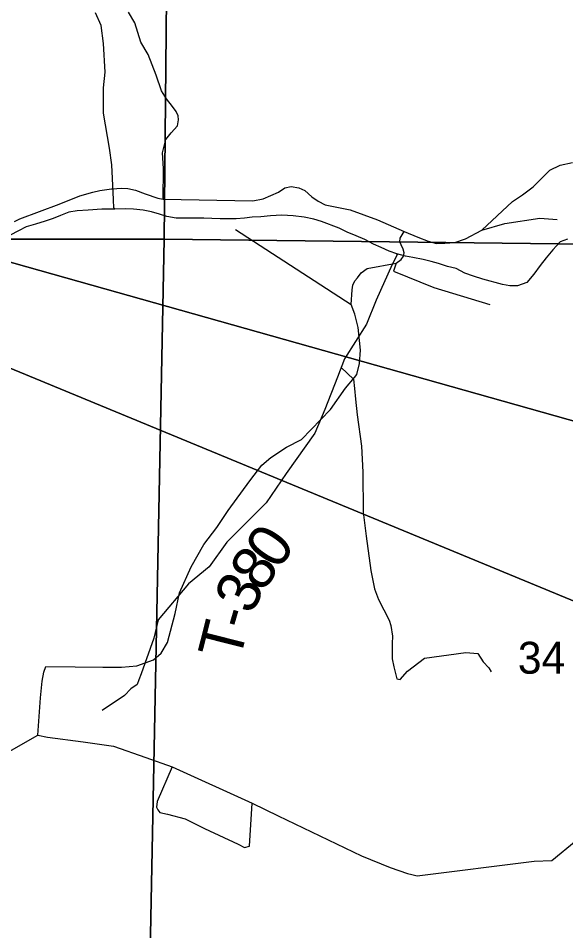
# Model space of a CAD drawing. Extents: x 0 to 34, y 0 to 22.
# Drawn here: x 6.245 to 6.964, y 16.204 to 17.402 of the extents above; entities that cross this region are included whole.
import ezdxf

# ---------------------------------------------------------------- set-up
doc = ezdxf.new("R2010")
doc.units = 0
for name, color, linetype in [('GM_X_County_Road', 7, 'Continuous'), ('GM_X_Minor_River', 7, 'Continuous'), ('GM_X_Section', 7, 'Continuous'), ('GM_X_Section_Text', 7, 'Continuous'), ('GM_X_Township_Road', 7, 'Continuous'), ('GM_X_Township_Road_Text', 7, 'Continuous'), ('SC_Shading1', 7, 'Continuous'), ('SH_Data', 7, 'Continuous')]:
    doc.layers.add(name, color=color, linetype=linetype)

msp = doc.modelspace()

# ---------------------------------------------------------------- linework, layer by layer
at = {"layer": 'GM_X_County_Road'}
for p, q in [((6.9435, 17.2023), (6.9567, 17.2088)), ((6.9567, 17.2088), (6.9733, 17.2121)), ((6.9212, 17.1802), (6.9435, 17.2023)), ((6.5953, 17.1792), (6.6035, 17.1807)), ((6.6035, 17.1807), (6.6138, 17.1792)), ((6.3261, 17.1683), (6.3431, 17.1733)), ((6.3431, 17.1733), (6.3524, 17.1753)), ((6.3524, 17.1753), (6.3677, 17.1775)), ((6.3677, 17.1775), (6.3687, 17.1776)), ((6.3687, 17.1776), (6.3803, 17.1787)), ((6.3803, 17.1787), (6.389, 17.1782)), ((6.389, 17.1782), (6.399, 17.176)), ((6.399, 17.176), (6.4116, 17.171)), ((6.4116, 17.171), (6.4285, 17.1654)), ((6.5666, 17.1645), (6.5868, 17.1735)), ((6.5868, 17.1735), (6.5953, 17.1792)), ((6.6138, 17.1792), (6.6215, 17.1757)), ((6.6215, 17.1757), (6.6305, 17.167)), ((6.8942, 17.1612), (6.9072, 17.17)), ((6.9072, 17.17), (6.9212, 17.1802)), ((6.2472, 17.1381), (6.2988, 17.1577)), ((6.2988, 17.1577), (6.3261, 17.1683)), ((6.4285, 17.1654), (6.4353, 17.164)), ((6.4353, 17.164), (6.5533, 17.1619)), ((6.5533, 17.1619), (6.5666, 17.1645)), ((6.6305, 17.167), (6.639, 17.1613)), ((6.639, 17.1613), (6.648, 17.1568)), ((6.648, 17.1568), (6.6812, 17.15)), ((6.8539, 17.1236), (6.8942, 17.1612)), ((6.6812, 17.15), (6.7171, 17.1368)), ((6.2402, 17.1346), (6.2472, 17.1381)), ((6.7171, 17.1368), (6.7518, 17.1217)), ((6.7518, 17.1217), (6.7701, 17.1142)), ((6.8325, 17.112), (6.8539, 17.1236)), ((6.7701, 17.1142), (6.7836, 17.1092)), ((6.7836, 17.1092), (6.7946, 17.106)), ((6.8183, 17.1071), (6.8325, 17.112)), ((6.7946, 17.106), (6.8054, 17.1065)), ((6.8054, 17.1065), (6.8183, 17.1071))]:
    msp.add_line(p, q, dxfattribs=at)
at = {"layer": 'GM_X_Minor_River'}
for p, q in [((6.3538, 17.3923), (6.3467, 17.4086)), ((6.3572, 17.3684), (6.3538, 17.3923)), ((6.359, 17.3307), (6.3572, 17.3684)), ((6.357, 17.3101), (6.359, 17.3307)), ((6.3572, 17.277), (6.357, 17.3101)), ((6.3648, 17.2311), (6.3572, 17.277)), ((6.3678, 17.2094), (6.3648, 17.2311)), ((6.3699, 17.1733), (6.3678, 17.2094)), ((6.3701, 17.1634), (6.3699, 17.1733)), ((6.3707, 17.1527), (6.3701, 17.1634)), ((6.3115, 17.1472), (6.3007, 17.1427)), ((6.3225, 17.1487), (6.3115, 17.1472)), ((6.3369, 17.1499), (6.3225, 17.1487)), ((6.3548, 17.1509), (6.3369, 17.1499)), ((6.3715, 17.151), (6.3548, 17.1509)), ((6.3722, 17.151), (6.3707, 17.1527)), ((6.3859, 17.1515), (6.3715, 17.151)), ((6.3966, 17.151), (6.3859, 17.1515)), ((6.4092, 17.1495), (6.3966, 17.151)), ((6.4199, 17.1476), (6.4092, 17.1495)), ((6.4306, 17.1445), (6.4199, 17.1476)), ((6.2804, 17.1352), (6.2675, 17.1314)), ((6.2909, 17.1386), (6.2804, 17.1352)), ((6.3007, 17.1427), (6.2909, 17.1386)), ((6.4402, 17.1414), (6.4306, 17.1445)), ((6.4525, 17.1391), (6.4402, 17.1414)), ((6.4642, 17.1394), (6.4525, 17.1391)), ((6.4764, 17.1391), (6.4642, 17.1394)), ((6.4886, 17.1394), (6.4764, 17.1391)), ((6.4992, 17.1386), (6.4886, 17.1394)), ((6.5103, 17.1382), (6.4992, 17.1386)), ((6.5198, 17.1381), (6.5103, 17.1382)), ((6.5312, 17.1385), (6.5198, 17.1381)), ((6.5422, 17.1392), (6.5312, 17.1385)), ((6.5524, 17.1403), (6.5422, 17.1392)), ((6.5638, 17.141), (6.5524, 17.1403)), ((6.5763, 17.1422), (6.5638, 17.141)), ((6.5911, 17.143), (6.5763, 17.1422)), ((6.6063, 17.1424), (6.5911, 17.143)), ((6.6205, 17.1405), (6.6063, 17.1424)), ((6.6331, 17.1379), (6.6205, 17.1405)), ((6.6434, 17.1348), (6.6331, 17.1379)), ((6.6665, 17.126), (6.6434, 17.1348)), ((6.2454, 17.1227), (6.2345, 17.117)), ((6.2555, 17.1276), (6.2454, 17.1227)), ((6.2675, 17.1314), (6.2555, 17.1276)), ((6.677, 17.1206), (6.6665, 17.126)), ((6.6889, 17.116), (6.677, 17.1206)), ((6.7001, 17.111), (6.6889, 17.116)), ((6.7116, 17.1049), (6.7001, 17.111)), ((6.9665, 17.1114), (6.9568, 17.108)), ((6.7217, 17.1007), (6.7116, 17.1049)), ((6.7324, 17.096), (6.7217, 17.1007)), ((6.9472, 17.0978), (6.9384, 17.0869)), ((6.9568, 17.108), (6.9472, 17.0978)), ((6.7424, 17.0925), (6.7324, 17.096)), ((6.7429, 17.0911), (6.7363, 17.0784)), ((6.7414, 17.0929), (6.7429, 17.0911)), ((6.7536, 17.0895), (6.7424, 17.0925)), ((6.7635, 17.0875), (6.7536, 17.0895)), ((6.7769, 17.0849), (6.7635, 17.0875)), ((6.7876, 17.0821), (6.7769, 17.0849)), ((6.9384, 17.0869), (6.9307, 17.0771)), ((6.7363, 17.0784), (6.7152, 17.0316)), ((6.7972, 17.0798), (6.7876, 17.0821)), ((6.8087, 17.0759), (6.7972, 17.0798)), ((6.8202, 17.0729), (6.8087, 17.0759)), ((6.8318, 17.0671), (6.8202, 17.0729)), ((6.9307, 17.0771), (6.9223, 17.0658)), ((6.8429, 17.0629), (6.8318, 17.0671)), ((6.8552, 17.0591), (6.8429, 17.0629)), ((6.9223, 17.0658), (6.9131, 17.0548)), ((6.8813, 17.0519), (6.8552, 17.0591)), ((6.8908, 17.0503), (6.8813, 17.0519)), ((6.9007, 17.0503), (6.8908, 17.0503)), ((6.9131, 17.0548), (6.9007, 17.0503)), ((6.7152, 17.0316), (6.7025, 16.9998)), ((6.7025, 16.9998), (6.6734, 16.9543)), ((6.6734, 16.9543), (6.6643, 16.9306)), ((6.6691, 16.943), (6.6856, 16.9279)), ((6.6643, 16.9306), (6.6477, 16.888)), ((6.6856, 16.9279), (6.6869, 16.9157)), ((6.6869, 16.9157), (6.6879, 16.9017)), ((6.6879, 16.9017), (6.6901, 16.8811)), ((6.6477, 16.888), (6.6346, 16.857)), ((6.6901, 16.8811), (6.6961, 16.8397)), ((6.6346, 16.857), (6.5969, 16.8038)), ((6.6961, 16.8397), (6.6975, 16.8059)), ((6.5969, 16.8038), (6.5708, 16.7653)), ((6.6975, 16.8059), (6.698, 16.7533)), ((6.5708, 16.7653), (6.5191, 16.7138)), ((6.698, 16.7533), (6.7019, 16.7218)), ((6.5191, 16.7138), (6.4958, 16.6815)), ((6.7019, 16.7218), (6.7083, 16.6766)), ((6.4958, 16.6815), (6.4686, 16.6589)), ((6.7083, 16.6766), (6.7129, 16.6527)), ((6.4686, 16.6589), (6.429, 16.6118)), ((6.7129, 16.6527), (6.7184, 16.6387)), ((6.7184, 16.6387), (6.7321, 16.6115)), ((6.429, 16.6118), (6.423, 16.5878)), ((6.7321, 16.6115), (6.7345, 16.6043)), ((6.7345, 16.6043), (6.7367, 16.5903)), ((6.423, 16.5878), (6.4064, 16.5411)), ((6.7367, 16.5903), (6.7361, 16.5807)), ((6.7361, 16.5807), (6.7364, 16.5606)), ((6.7364, 16.5606), (6.7385, 16.55)), ((6.7564, 16.5445), (6.7787, 16.5613)), ((6.7787, 16.5613), (6.833, 16.569)), ((6.833, 16.569), (6.8486, 16.5674)), ((6.8486, 16.5674), (6.8559, 16.5565)), ((6.7385, 16.55), (6.7422, 16.5344)), ((6.8559, 16.5565), (6.8632, 16.549)), ((6.8632, 16.549), (6.8664, 16.5437)), ((6.4064, 16.5411), (6.4035, 16.533)), ((6.7422, 16.5344), (6.7467, 16.5333)), ((6.7467, 16.5333), (6.7564, 16.5445)), ((6.4013, 16.5269), (6.3931, 16.5214)), ((6.4035, 16.533), (6.4013, 16.5269)), ((6.3846, 16.5125), (6.3551, 16.4926)), ((6.3931, 16.5214), (6.3846, 16.5125))]:
    msp.add_line(p, q, dxfattribs=at)
at = {"layer": 'GM_X_Section'}
for p, q in [((6.4465, 18.0895), (6.4366, 17.1114)), ((6.4366, 17.1114), (6.4465, 18.0895)), ((6.4366, 17.1114), (5.492, 17.1117)), ((5.492, 17.1117), (6.4366, 17.1114)), ((6.4161, 16.0534), (6.4366, 17.1114)), ((6.4366, 17.1114), (6.4161, 16.0534)), ((7.441, 17.0998), (6.4366, 17.1114)), ((6.4366, 17.1114), (7.441, 17.0998))]:
    msp.add_line(p, q, dxfattribs=at)
at = {"layer": 'GM_X_Township_Road'}
for p, q in [((6.3983, 17.3957), (6.3898, 17.4096)), ((6.4062, 17.3704), (6.3983, 17.3957)), ((6.4155, 17.3539), (6.4062, 17.3704)), ((6.4262, 17.3271), (6.4155, 17.3539)), ((6.4332, 17.3065), (6.4262, 17.3271)), ((6.4398, 17.2959), (6.4332, 17.3065)), ((6.4476, 17.2856), (6.4398, 17.2959)), ((6.4525, 17.2794), (6.4476, 17.2856)), ((6.4552, 17.2737), (6.4525, 17.2794)), ((6.454, 17.2606), (6.4555, 17.2685)), ((6.4555, 17.2685), (6.4552, 17.2737)), ((6.4458, 17.2511), (6.454, 17.2606)), ((6.4347, 17.2251), (6.4388, 17.2425)), ((6.4388, 17.2425), (6.4458, 17.2511)), ((6.4356, 17.2043), (6.4347, 17.2251)), ((6.4353, 17.164), (6.4356, 17.2043)), ((6.8843, 17.1322), (6.9302, 17.1391)), ((6.9302, 17.1391), (6.953, 17.1375)), ((6.5306, 17.1245), (6.6822, 17.0257)), ((6.7465, 17.113), (6.7518, 17.1217)), ((6.8539, 17.1236), (6.8843, 17.1322)), ((6.7463, 17.1083), (6.7465, 17.113)), ((6.7481, 17.1042), (6.7463, 17.1083)), ((6.7505, 17.0983), (6.7481, 17.1042)), ((6.7519, 17.0937), (6.7505, 17.0983)), ((6.7413, 17.0803), (6.7479, 17.0851)), ((6.7479, 17.0851), (6.751, 17.0893)), ((6.751, 17.0893), (6.7519, 17.0937)), ((6.6954, 17.0674), (6.7035, 17.0729)), ((6.7035, 17.0729), (6.7413, 17.0803)), ((6.7413, 17.0803), (6.738, 17.0697)), ((6.6871, 17.0569), (6.6908, 17.0608)), ((6.6908, 17.0608), (6.6954, 17.0674)), ((6.738, 17.0697), (6.791, 17.0482)), ((6.6837, 17.0449), (6.6846, 17.0511)), ((6.6846, 17.0511), (6.6871, 17.0569)), ((6.6822, 17.0257), (6.6837, 17.0449)), ((6.791, 17.0482), (6.8644, 17.026)), ((6.6873, 17.0131), (6.6822, 17.0257)), ((6.6917, 16.9955), (6.6873, 17.0131)), ((6.6947, 16.966), (6.6917, 16.9955)), ((6.6932, 16.9482), (6.6947, 16.966)), ((6.6896, 16.934), (6.6932, 16.9482)), ((6.6751, 16.9162), (6.6865, 16.9301)), ((6.6865, 16.9301), (6.6896, 16.934)), ((6.6551, 16.8881), (6.6751, 16.9162)), ((6.6169, 16.8485), (6.6551, 16.8881)), ((6.5975, 16.8385), (6.6169, 16.8485)), ((6.577, 16.825), (6.5975, 16.8385)), ((6.5652, 16.815), (6.577, 16.825)), ((6.5494, 16.7942), (6.5652, 16.815)), ((6.5209, 16.7553), (6.5494, 16.7942)), ((6.5059, 16.7331), (6.5209, 16.7553)), ((6.4886, 16.7106), (6.5059, 16.7331)), ((6.4721, 16.6812), (6.4886, 16.7106)), ((6.4568, 16.6472), (6.4721, 16.6812)), ((6.451, 16.6201), (6.4568, 16.6472)), ((6.441, 16.582), (6.451, 16.6201)), ((6.4328, 16.5682), (6.441, 16.582)), ((6.4008, 16.5512), (6.4225, 16.5591)), ((6.4225, 16.5591), (6.4328, 16.5682)), ((6.2786, 16.5431), (6.2813, 16.5506)), ((6.2813, 16.5506), (6.3196, 16.5502)), ((6.3196, 16.5502), (6.3563, 16.5495)), ((6.3563, 16.5495), (6.3805, 16.5497)), ((6.3805, 16.5497), (6.4008, 16.5512)), ((6.2763, 16.5311), (6.2786, 16.5431)), ((6.2741, 16.5095), (6.2763, 16.5311)), ((6.2708, 16.4605), (6.2741, 16.5095)), ((6.097, 16.3616), (6.2708, 16.4605)), ((6.2708, 16.4605), (6.2836, 16.4578)), ((6.2836, 16.4578), (6.3302, 16.4518)), ((6.3302, 16.4518), (6.3703, 16.4458)), ((6.3703, 16.4458), (6.4124, 16.4309)), ((6.4124, 16.4309), (6.4472, 16.4186)), ((6.4472, 16.4186), (6.4276, 16.3733)), ((6.4472, 16.4186), (6.5522, 16.3711)), ((6.4276, 16.3733), (6.4265, 16.3657)), ((6.549, 16.3147), (6.5522, 16.3711)), ((6.5522, 16.3711), (6.5866, 16.3545)), ((6.4265, 16.3657), (6.4282, 16.3623)), ((6.4282, 16.3623), (6.4308, 16.3588)), ((6.4308, 16.3588), (6.4411, 16.3566)), ((6.4411, 16.3566), (6.4641, 16.3507)), ((6.5866, 16.3545), (6.6958, 16.3021)), ((6.4641, 16.3507), (6.4897, 16.3378)), ((6.4897, 16.3378), (6.534, 16.3174)), ((6.946, 16.2957), (6.9777, 16.322)), ((6.534, 16.3174), (6.5423, 16.3131)), ((6.5423, 16.3131), (6.549, 16.3147)), ((6.6958, 16.3021), (6.7334, 16.2867)), ((6.769, 16.2758), (6.9227, 16.2949)), ((6.9227, 16.2949), (6.946, 16.2957)), ((6.7334, 16.2867), (6.7564, 16.2789)), ((6.7564, 16.2789), (6.7622, 16.2775)), ((6.7622, 16.2775), (6.769, 16.2758))]:
    msp.add_line(p, q, dxfattribs=at)
at = {"layer": 'SC_Shading1'}
msp.add_lwpolyline([(10.3861, 15.9111), (10.3861, 15.2276), (5.1721, 17.3806)], close=True, dxfattribs=at)
at = {"layer": 'SH_Data'}
msp.add_lwpolyline([(10.3861, 15.9111), (5.1721, 17.3806), (10.3861, 15.2276)], dxfattribs=at)

# ---------------------------------------------------------------- texts
at = {"layer": 'GM_X_Section_Text'}
msp.add_text('34', height=0.04186, rotation=0, dxfattribs=at).set_placement((6.9013, 16.5411))
at = {"layer": 'GM_X_Township_Road_Text'}
for s, rotation, p in [('0', 55.3505, (6.5863, 16.6757)), ('8', 54.3177, (6.5652, 16.6464)), ('3', 64.7174, (6.5516, 16.6171)), ('-', 73.8637, (6.546, 16.5969)), ('T', 75.811, (6.5357, 16.5562))]:
    msp.add_text(s, height=0.0568, rotation=rotation, dxfattribs=at).set_placement(p)

doc.saveas('drawing.dxf')
